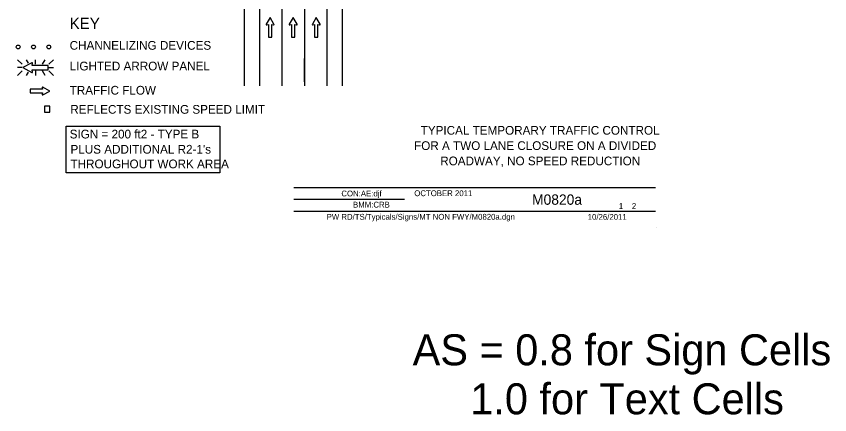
# Model space of a CAD drawing. Extents: x 16745 to 18475, y 7012 to 8195.
# Drawn here: x 16745 to 17611, y 7012 to 7436 of the extents above; entities that cross this region are included whole.
import ezdxf

# ---------------------------------------------------------------- set-up
doc = ezdxf.new("R2010")
doc.units = 0
for name, color, linetype in [('ALI_LEGAL_EX', 7, 'Continuous'), ('BORDER', 7, 'Continuous'), ('BORDER_SIGNAL_WO', 7, 'Continuous'), ('MT_SCRATCH_LEVEL_E', 7, 'Continuous'), ('PAVT_EDGE_EX', 7, 'Continuous'), ('TRAFFIC_SIGNS_PR', 7, 'Continuous'), ('TYPICAL_TEXT_DIMEN_EX', 7, 'Continuous')]:
    doc.layers.add(name, color=color, linetype=linetype)

msp = doc.modelspace()

# ---------------------------------------------------------------- linework, layer by layer
at = {"layer": 'ALI_LEGAL_EX'}
for p, q in [((17027.37, 8191.42), (17027.37, 7362.23)), ((17051.37, 8191.42), (17051.37, 7362.23)), ((17051.37, 8191.42), (17051.37, 7362.23))]:
    msp.add_line(p, q, dxfattribs=at)
for points in [[(17027.37, 7391.42), (17027.37, 7366.42)], [(17051.37, 7366.42), (17051.37, 7391.42)], [(17051.37, 7391.42), (17051.37, 7366.42)]]:
    msp.add_lwpolyline(points, dxfattribs=at)
at = {"layer": 'BORDER'}
for p, q in [((17040.04, 7253.75), (17425.04, 7253.75)), ((17040.04, 7241.25), (17158.04, 7241.25)), ((17040.04, 7228.75), (17425.04, 7228.75)), ((17425.84, 7210.65), (17425.84, 7210.65))]:
    msp.add_line(p, q, dxfattribs=at)
at = {"layer": 'MT_SCRATCH_LEVEL_E'}
for p, q in [((17014.8, 7435.06), (17010.69, 7427.82)), ((17014.8, 7435.06), (17010.69, 7427.82)), ((17018.95, 7427.82), (17014.8, 7435.06)), ((17018.95, 7427.82), (17014.8, 7435.06)), ((17039.33, 7435.06), (17035.22, 7427.82)), ((17039.33, 7435.06), (17035.22, 7427.82)), ((17043.48, 7427.82), (17039.33, 7435.06)), ((17043.48, 7427.82), (17039.33, 7435.06)), ((17063.89, 7435.06), (17059.78, 7427.82)), ((17063.89, 7435.06), (17059.78, 7427.82)), ((17068.04, 7427.82), (17063.89, 7435.06)), ((17068.04, 7427.82), (17063.89, 7435.06)), ((17011.17, 7427.13), (17012.95, 7427.45)), ((17011.17, 7427.13), (17012.95, 7427.45)), ((17012.95, 7427.45), (17012.95, 7414.19)), ((17012.95, 7427.45), (17012.95, 7414.19)), ((17016.69, 7414.19), (17016.69, 7427.45)), ((17016.69, 7427.45), (17018.47, 7427.13)), ((17016.69, 7414.19), (17016.69, 7427.45)), ((17016.69, 7427.45), (17018.47, 7427.13)), ((17035.7, 7427.13), (17037.48, 7427.45)), ((17035.7, 7427.13), (17037.48, 7427.45)), ((17037.48, 7427.45), (17037.48, 7414.19)), ((17037.48, 7427.45), (17037.48, 7414.19)), ((17041.22, 7414.19), (17041.22, 7427.45)), ((17041.22, 7427.45), (17043, 7427.13)), ((17041.22, 7414.19), (17041.22, 7427.45)), ((17041.22, 7427.45), (17043, 7427.13)), ((17060.26, 7427.13), (17062.04, 7427.45)), ((17060.26, 7427.13), (17062.04, 7427.45)), ((17062.04, 7427.45), (17062.04, 7414.19)), ((17062.04, 7427.45), (17062.04, 7414.19)), ((17065.78, 7414.19), (17065.78, 7427.45)), ((17065.78, 7427.45), (17067.56, 7427.13)), ((17065.78, 7414.19), (17065.78, 7427.45)), ((17065.78, 7427.45), (17067.56, 7427.13)), ((17012.95, 7414.19), (17016.69, 7414.19)), ((17012.95, 7414.19), (17016.69, 7414.19)), ((17037.48, 7414.19), (17041.22, 7414.19)), ((17037.48, 7414.19), (17041.22, 7414.19)), ((17062.04, 7414.19), (17065.78, 7414.19)), ((17062.04, 7414.19), (17065.78, 7414.19)), ((16772.31, 7360.27), (16772.63, 7358.5)), ((16772.31, 7360.27), (16772.63, 7358.5)), ((16780.24, 7356.65), (16773, 7360.76)), ((16780.24, 7356.65), (16773, 7360.76)), ((16772.63, 7358.5), (16759.37, 7358.5)), ((16759.37, 7358.5), (16759.37, 7354.76)), ((16772.63, 7358.5), (16759.37, 7358.5)), ((16759.37, 7358.5), (16759.37, 7354.76)), ((16759.37, 7354.76), (16772.63, 7354.76)), ((16759.37, 7354.76), (16772.63, 7354.76)), ((16772.63, 7354.76), (16772.31, 7352.98)), ((16772.63, 7354.76), (16772.31, 7352.98)), ((16773, 7352.5), (16780.24, 7356.65)), ((16773, 7352.5), (16780.24, 7356.65))]:
    msp.add_line(p, q, dxfattribs=at)
for centre, start, end in [((17011.1, 7427.59), 150.42484, 279.96381), ((17011.1, 7427.59), 150.42484, 279.96381), ((17018.54, 7427.59), 260.03619, 29.77312), ((17018.54, 7427.59), 260.03619, 29.77312), ((17035.63, 7427.59), 150.42484, 279.96381), ((17035.63, 7427.59), 150.42484, 279.96381), ((17043.07, 7427.59), 260.03619, 29.77312), ((17043.07, 7427.59), 260.03619, 29.77312), ((17060.19, 7427.59), 150.42484, 279.96381), ((17060.19, 7427.59), 150.42484, 279.96381), ((17067.63, 7427.59), 260.03619, 29.77312), ((17067.63, 7427.59), 260.03619, 29.77312), ((16772.77, 7360.35), 60.42484, 189.96381), ((16772.77, 7360.35), 60.42484, 189.96381), ((16772.77, 7352.91), 170.03619, 299.77312), ((16772.77, 7352.91), 170.03619, 299.77312)]:
    msp.add_arc(centre, 0.463, start, end, dxfattribs=at)
at = {"layer": 'PAVT_EDGE_EX'}
for p, q in [((16987.37, 8191.42), (16987.37, 7362.23)), ((17003.37, 8191.42), (17003.37, 7362.23)), ((17003.37, 8191.42), (17003.37, 7362.23)), ((17075.37, 8191.42), (17075.37, 7362.23)), ((17091.37, 8191.42), (17091.37, 7362.23))]:
    msp.add_line(p, q, dxfattribs=at)
at = {"layer": 'TRAFFIC_SIGNS_PR'}
for p, q in [((16746.05, 7390.03), (16750.98, 7385.1)), ((16757.81, 7386.21), (16755.61, 7390.03)), ((16765.13, 7385.1), (16765.13, 7390.03)), ((16772.37, 7385.1), (16775.22, 7390.03)), ((16779.28, 7385.1), (16784.22, 7390.03)), ((16750.98, 7381.54), (16746.05, 7381.54)), ((16746.05, 7373.05), (16750.98, 7377.98)), ((16765.13, 7377.98), (16765.13, 7373.05)), ((16775.26, 7373.05), (16772.41, 7377.98)), ((16779.28, 7381.54), (16784.22, 7381.54)), ((16779.28, 7377.98), (16784.22, 7373.05)), ((16755.56, 7373.05), (16757.67, 7376.71))]:
    msp.add_line(p, q, dxfattribs=at)
for points in [[(16761.06, 7386.82), (16751.77, 7381.54), (16761.06, 7376.22)], [(16761.94, 7376.85), (16761.53, 7379.11), (16778.55, 7379.11), (16778.55, 7383.92), (16761.53, 7383.92), (16761.94, 7386.2)]]:
    msp.add_lwpolyline(points, dxfattribs=at)
msp.add_lwpolyline([(16774.6, 7334.27), (16780.19, 7334.27), (16780.19, 7340.44), (16774.6, 7340.44)], close=True, dxfattribs=at)
for centre in [(16746.61, 7403.57), (16762.91, 7403.57), (16779.21, 7403.57)]:
    msp.add_circle(centre, 2, dxfattribs=at)
for centre, radius, start, end in [((16761.35, 7386.29), 0.598, 350.73078, 118.89165), ((16761.35, 7376.74), 0.597, 241.48329, 9.95933)]:
    msp.add_arc(centre, radius, start, end, dxfattribs=at)
at = {"layer": 'TYPICAL_TEXT_DIMEN_EX'}
msp.add_lwpolyline([(16797.68, 7319.26), (16961.34, 7319.26), (16961.34, 7269.35), (16797.68, 7269.35)], close=True, dxfattribs=at)

# ---------------------------------------------------------------- texts
at = {"layer": 'BORDER'}
for s, p in [('TYPICAL TEMPORARY TRAFFIC CONTROL', (17175.11, 7310.08)), ('FOR A TWO LANE CLOSURE ON A DIVIDED', (17168.09, 7293.78)), ('ROADWAY, NO SPEED REDUCTION', (17195.92, 7277.48))]:
    msp.add_text(s, height=9.3, dxfattribs=at).set_placement(p)
at = {"layer": 'BORDER_SIGNAL_WO'}
for s, height, p in [('CON:AE:djf', 6.2, (17090.69, 7244.31)), ('    OCTOBER 2011    ', 6.2, (17159.08, 7244.59)), ('    M0820a   ', 11, (17277.32, 7235.43)), ('BMM:CRB   ', 6.2, (17103.1, 7232.42)), (' 1    2 ', 6.2, (17383.74, 7230.95)), ('PW RD/TS/Typicals/Signs/MT NON FWY/M0820a.dgn    ', 6.2, (17075.01, 7219.49)), ('10/26/2011    ', 6.2, (17352.93, 7219.38)), ('AS = 0.8 for Sign Cells', 33.0301, (17166.51, 7064.32)), ('     1.0 for Text Cells', 33.0301, (17166.51, 7012.09))]:
    msp.add_text(s, height=height, dxfattribs=at).set_placement(p)
at = {"layer": 'TYPICAL_TEXT_DIMEN_EX'}
for s, height, p in [('KEY', 12, (16801.45, 7422.68)), ('CHANNELIZING DEVICES', 9.3, (16801.45, 7400.63)), ('LIGHTED ARROW PANEL', 9.3, (16801.45, 7378.58)), ('TRAFFIC FLOW', 9.3, (16801.45, 7352.78)), ('REFLECTS EXISTING SPEED LIMIT', 9.3, (16802.14, 7332.43)), ('SIGN = 200 ft2 - TYPE B', 9.3, (16801.45, 7306.09)), ("PLUS ADDITIONAL R2-1's", 9.3, (16802.33, 7289.88)), ('THROUGHOUT WORK AREA', 9.3, (16802.33, 7274.28))]:
    msp.add_text(s, height=height, dxfattribs=at).set_placement(p)

doc.saveas('drawing.dxf')
